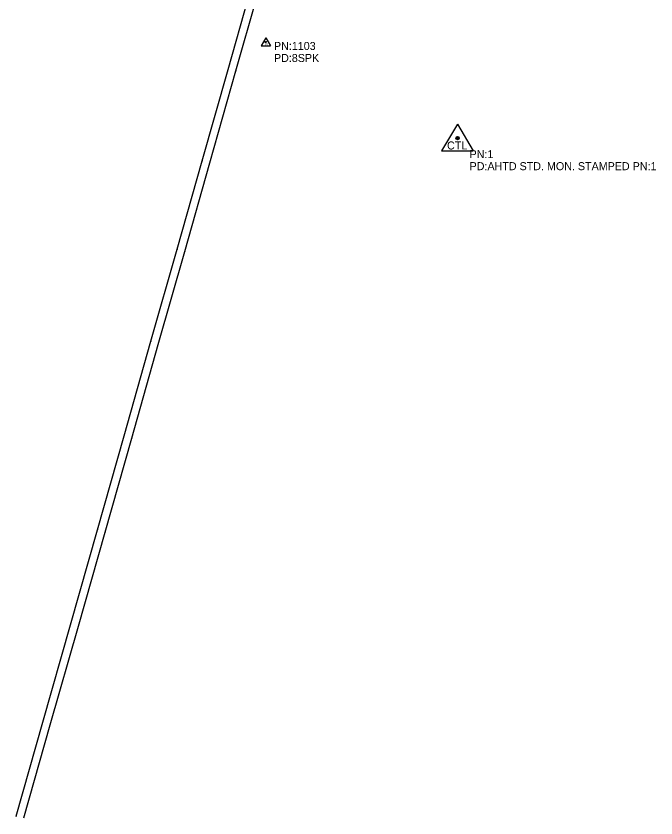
# Model space of a CAD drawing. Extents: x 929765 to 934279, y 1533086 to 1541189.
# Drawn here: x 931752 to 932151, y 1536452 to 1536953 of the extents above; entities that cross this region are included whole.
import ezdxf

# ---------------------------------------------------------------- set-up
doc = ezdxf.new("R2010")
doc.units = 0
for name, color, linetype in [('S_MSC_PT_SYM', 7, 'Continuous'), ('S_PRIMARY_CTL', 7, 'Continuous'), ('S_PRIMARY_CTL_ANNOT', 7, 'Continuous'), ('S_RAILROAD', 7, 'Continuous'), ('S_SECONDARY_CTL', 7, 'Continuous'), ('S_SECONDARY_CTL_ANNOT', 7, 'Continuous')]:
    doc.layers.add(name, color=color, linetype=linetype)

msp = doc.modelspace()

# ---------------------------------------------------------------- linework, layer by layer
at = {"layer": 'S_MSC_PT_SYM'}
for points in [[(931884, 1536919.75), (931884, 1536919.8), (931884, 1536919.75), (931883.95, 1536919.75), (931884, 1536919.75), (931884, 1536919.7), (931884, 1536919.75), (931884.05, 1536919.75)], [(931888.87, 1536918.86), (931888.87, 1536918.91), (931888.87, 1536918.86), (931888.82, 1536918.86), (931888.87, 1536918.86), (931888.87, 1536918.81), (931888.87, 1536918.86), (931888.92, 1536918.86)], [(931867.84, 1536862.63), (931867.84, 1536862.68), (931867.84, 1536862.63), (931867.79, 1536862.63), (931867.84, 1536862.63), (931867.84, 1536862.58), (931867.84, 1536862.63), (931867.89, 1536862.63)], [(931872.63, 1536861.5), (931872.63, 1536861.55), (931872.63, 1536861.5), (931872.58, 1536861.5), (931872.63, 1536861.5), (931872.63, 1536861.45), (931872.63, 1536861.5), (931872.68, 1536861.5)], [(931852.23, 1536807.47), (931852.23, 1536807.52), (931852.23, 1536807.47), (931852.18, 1536807.47), (931852.23, 1536807.47), (931852.23, 1536807.42), (931852.23, 1536807.47), (931852.28, 1536807.47)], [(931856.95, 1536806.15), (931856.95, 1536806.2), (931856.95, 1536806.15), (931856.9, 1536806.15), (931856.95, 1536806.15), (931856.95, 1536806.1), (931856.95, 1536806.15), (931857, 1536806.15)], [(931835.85, 1536750), (931835.85, 1536750.05), (931835.85, 1536750), (931835.8, 1536750), (931835.85, 1536750), (931835.85, 1536749.95), (931835.85, 1536750), (931835.9, 1536750)], [(931840.38, 1536747.96), (931840.38, 1536748.01), (931840.38, 1536747.96), (931840.33, 1536747.96), (931840.38, 1536747.96), (931840.38, 1536747.91), (931840.38, 1536747.96), (931840.43, 1536747.96)], [(931819.1, 1536690.93), (931819.1, 1536690.98), (931819.1, 1536690.93), (931819.05, 1536690.93), (931819.1, 1536690.93), (931819.1, 1536690.88), (931819.1, 1536690.93), (931819.15, 1536690.93)], [(931823.84, 1536689.57), (931823.84, 1536689.62), (931823.84, 1536689.57), (931823.79, 1536689.57), (931823.84, 1536689.57), (931823.84, 1536689.52), (931823.84, 1536689.57), (931823.89, 1536689.57)], [(931802.44, 1536632.3), (931802.44, 1536632.35), (931802.44, 1536632.3), (931802.39, 1536632.3), (931802.44, 1536632.3), (931802.44, 1536632.25), (931802.44, 1536632.3), (931802.49, 1536632.3)], [(931807.19, 1536630.84), (931807.19, 1536630.89), (931807.19, 1536630.84), (931807.14, 1536630.84), (931807.19, 1536630.84), (931807.19, 1536630.79), (931807.19, 1536630.84), (931807.24, 1536630.84)], [(931785.58, 1536572.88), (931785.58, 1536572.93), (931785.58, 1536572.88), (931785.53, 1536572.88), (931785.58, 1536572.88), (931785.58, 1536572.83), (931785.58, 1536572.88), (931785.63, 1536572.88)], [(931790.55, 1536572.12), (931790.55, 1536572.17), (931790.55, 1536572.12), (931790.5, 1536572.12), (931790.55, 1536572.12), (931790.55, 1536572.07), (931790.55, 1536572.12), (931790.6, 1536572.12)], [(931768.38, 1536512.08), (931768.38, 1536512.13), (931768.38, 1536512.08), (931768.33, 1536512.08), (931768.38, 1536512.08), (931768.38, 1536512.03), (931768.38, 1536512.08), (931768.43, 1536512.08)], [(931773.06, 1536510.43), (931773.06, 1536510.48), (931773.06, 1536510.43), (931773.01, 1536510.43), (931773.06, 1536510.43), (931773.06, 1536510.38), (931773.06, 1536510.43), (931773.11, 1536510.43)], [(931751.71, 1536453.34), (931751.71, 1536453.39), (931751.71, 1536453.34), (931751.66, 1536453.34), (931751.71, 1536453.34), (931751.71, 1536453.29), (931751.71, 1536453.34), (931751.76, 1536453.34)], [(931756.53, 1536452.33), (931756.53, 1536452.38), (931756.53, 1536452.33), (931756.48, 1536452.33), (931756.53, 1536452.33), (931756.53, 1536452.28), (931756.53, 1536452.33), (931756.58, 1536452.33)]]:
    msp.add_lwpolyline(points, dxfattribs=at)
at = {"layer": 'S_PRIMARY_CTL'}
for p, q in [((932027.26, 1536885.59), (932017.23, 1536869.07)), ((932027.26, 1536885.59), (932037.08, 1536869.07)), ((932017.23, 1536869.07), (932037.08, 1536869.07))]:
    msp.add_line(p, q, dxfattribs=at)
for radius in [1.04, 0.609, 0.344]:
    msp.add_circle((932027.26, 1536876.89), radius, dxfattribs=at)
at = {"layer": 'S_RAILROAD'}
for p, q in [((931884, 1536919.75), (931899.27, 1536973.69)), ((931888.87, 1536918.86), (931903.88, 1536971.99)), ((931867.84, 1536862.63), (931884, 1536919.75)), ((931872.63, 1536861.5), (931888.87, 1536918.86)), ((931852.23, 1536807.47), (931867.84, 1536862.63)), ((931856.95, 1536806.15), (931872.63, 1536861.5)), ((931835.85, 1536750), (931852.23, 1536807.47)), ((931840.38, 1536747.96), (931856.95, 1536806.15)), ((931819.1, 1536690.93), (931835.85, 1536750)), ((931823.84, 1536689.57), (931840.38, 1536747.96)), ((931802.44, 1536632.3), (931819.1, 1536690.93)), ((931807.19, 1536630.84), (931823.84, 1536689.57)), ((931785.58, 1536572.88), (931802.44, 1536632.3)), ((931790.55, 1536572.12), (931807.19, 1536630.84)), ((931768.38, 1536512.08), (931785.58, 1536572.88)), ((931773.06, 1536510.43), (931790.55, 1536572.12)), ((931751.71, 1536453.34), (931768.38, 1536512.08)), ((931756.53, 1536452.33), (931773.06, 1536510.43))]:
    msp.add_line(p, q, dxfattribs=at)
at = {"layer": 'S_SECONDARY_CTL'}
for p, q in [((931907.65, 1536939.58), (931904.64, 1536934.63)), ((931907.65, 1536939.58), (931910.59, 1536934.63)), ((931904.64, 1536934.63), (931910.59, 1536934.63))]:
    msp.add_line(p, q, dxfattribs=at)
for radius in [0.311, 0.183, 0.103]:
    msp.add_circle((931907.65, 1536936.97), radius, dxfattribs=at)

# ---------------------------------------------------------------- texts
at = {"layer": 'S_PRIMARY_CTL'}
msp.add_text('CTL', height=5, rotation=360, dxfattribs=at).set_placement((932020.67, 1536869.81))
at = {"layer": 'S_PRIMARY_CTL_ANNOT'}
for s, p in [('PN:1', (932034.76, 1536864.39)), ('PD:AHTD STD. MON. STAMPED PN:1', (932034.76, 1536856.89))]:
    msp.add_text(s, height=5, dxfattribs=at).set_placement(p)
at = {"layer": 'S_SECONDARY_CTL'}
msp.add_text('TV', height=1.5, rotation=360, dxfattribs=at).set_placement((931906.44, 1536934.96))
at = {"layer": 'S_SECONDARY_CTL_ANNOT'}
for s, p in [('PN:1103', (931912.65, 1536931.97)), ('PD:8SPK', (931912.65, 1536924.47))]:
    msp.add_text(s, height=5, dxfattribs=at).set_placement(p)

doc.saveas('drawing.dxf')
